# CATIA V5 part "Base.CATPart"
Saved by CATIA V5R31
Part number: Base
Bounding box of the stored display mesh (mm): x -30 to 30, y -60 to 60, z -85 to -20
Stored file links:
  D:\PROJECTS\Project 2021\US EDITION\CATIA V5 6R 2021\Resources\Part Files\c12_catia_v5_6r2021_prt\c12_catia_v5-6r2021 figr_12-35\Base.CATPart
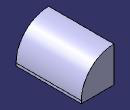
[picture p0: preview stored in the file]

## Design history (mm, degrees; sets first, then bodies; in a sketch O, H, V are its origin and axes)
Body1 (main body)
  Sketch1 on xy-plane, origin (0, 0, 0), H (1, 0, 0), V (0, 1, 0)
    line L1 (30, 60) -> (30, -60)
    line L2 (30, -60) -> (-30, -60)
    line L3 (-30, -60) -> (-30, 60)
    line L4 (-30, 60) -> (30, 60)
    length L2 = 60
    length L3 = 120
    vertical: L1 V, L3 V
    horizontal: L2 H, L4 H
    equidistance: L1 L3 O, L2 L4 O
  Pad1: profile Sketch1, direction (0, 0, -1), length 85, opposite side length -20
  Fillet1: radius 60, on edge [face of Pad1 | face of Pad1]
